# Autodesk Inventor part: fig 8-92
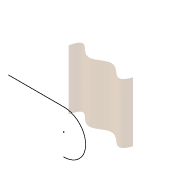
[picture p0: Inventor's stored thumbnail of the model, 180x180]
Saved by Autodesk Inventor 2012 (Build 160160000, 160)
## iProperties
Shininess: 64.0
Length Units: 11269
Angle Units: 11279
Time Units: 11290
Mass Units: 11283
Length Display Precision: 3
Angle Display Precision: 2
Compacted: True
Part Number: fig 8-92
Document SubType Name: Modeling
Created: 2003-08
Designer: Owner
Manufacturer: Standard
Standards Organization: Custom
Density: 1 g/cm^3
Material: Default
Density: 0.0
Volumn: 0.0
Area: 0.0
PropertySet Name: Model Information
Control State: 0
Master: False
Checked Out: False
Author: Owner
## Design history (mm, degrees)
sketch "Sketch1"
  geometry: 7 further points
  constraints: 7 other
  dimensions: "d0" = 80 horizontal distance of point (40, 1.742) point (-40, -4.065); "d1" = 40 horizontal distance of point (0, 0) point (-40, -4.065)
extrude_surface "ExtrusionSrf1" sketch "Sketch1" dims "d2" = 80, "d3" = 0
sketch "Sketch2"
  geometry: L1 (40, 0)-(40, -40) reference; L2 (-40, 0)-(-40, -40) reference; 7 further points
  constraints: 2 point on line, 7 other
extrude_surface "ExtrusionSrf2" sketch "Sketch2" dims "d4" = 80, "d5" = 0
workplane "Work Plane1"
sketch "Sketch4"
  geometry: L1 (70.027, 16.004)-(-4, 16.004); A1 r 29.004 centre (-4, -13) between (-4, 16.004) and (-2.981, -41.986)
  constraints: 2 end point, 2 point on circle, 1 centre point, 1 horizontal, 1 tangent
body "Srf1"
body "Srf2"
other parameters: "d6" = -54.75
